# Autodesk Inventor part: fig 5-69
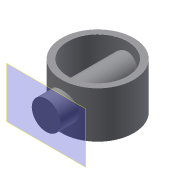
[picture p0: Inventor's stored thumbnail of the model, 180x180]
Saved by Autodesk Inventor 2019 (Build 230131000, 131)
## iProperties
Shininess: 64.0
Length Units: 11269
Angle Units: 11279
Time Units: 11290
Mass Units: 11283
Length Display Precision: 3
Angle Display Precision: 2
Compacted: True
Part Number: fig 5-69
Document SubType Name: Modeling
Created: 2002-12
Designer: deepak
Density: 1 g/cm^3
Material: Generic
Appearance: Default
Density: 0.0
Volumn: 0.0
Area: 0.0
PropertySet Name: Model Information
Control State: 0
Master: False
Checked Out: False
Author: deepak
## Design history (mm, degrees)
sketch "Sketch1"
  geometry: C1 r 23.454 at (0, 0); C2 r 19.43 at (0, 0)
  constraints: 2 centre point, 1 coincident, 1 concentric
extrude "Extrusion1" new body sketch "Sketch1" stored distance "d0" = 30; taper "d1" = 0 deg
workplane "Work Plane1"
workplane "Work Plane2"
sketch "Sketch2"
  geometry: C1 r 9.343 at (0, 0)
  constraints: 1 centre point
extrude "Extrusion2" join sketch "Sketch2" stored distance "d4" = 10; taper "d5" = 0 deg
body "Solid1"
